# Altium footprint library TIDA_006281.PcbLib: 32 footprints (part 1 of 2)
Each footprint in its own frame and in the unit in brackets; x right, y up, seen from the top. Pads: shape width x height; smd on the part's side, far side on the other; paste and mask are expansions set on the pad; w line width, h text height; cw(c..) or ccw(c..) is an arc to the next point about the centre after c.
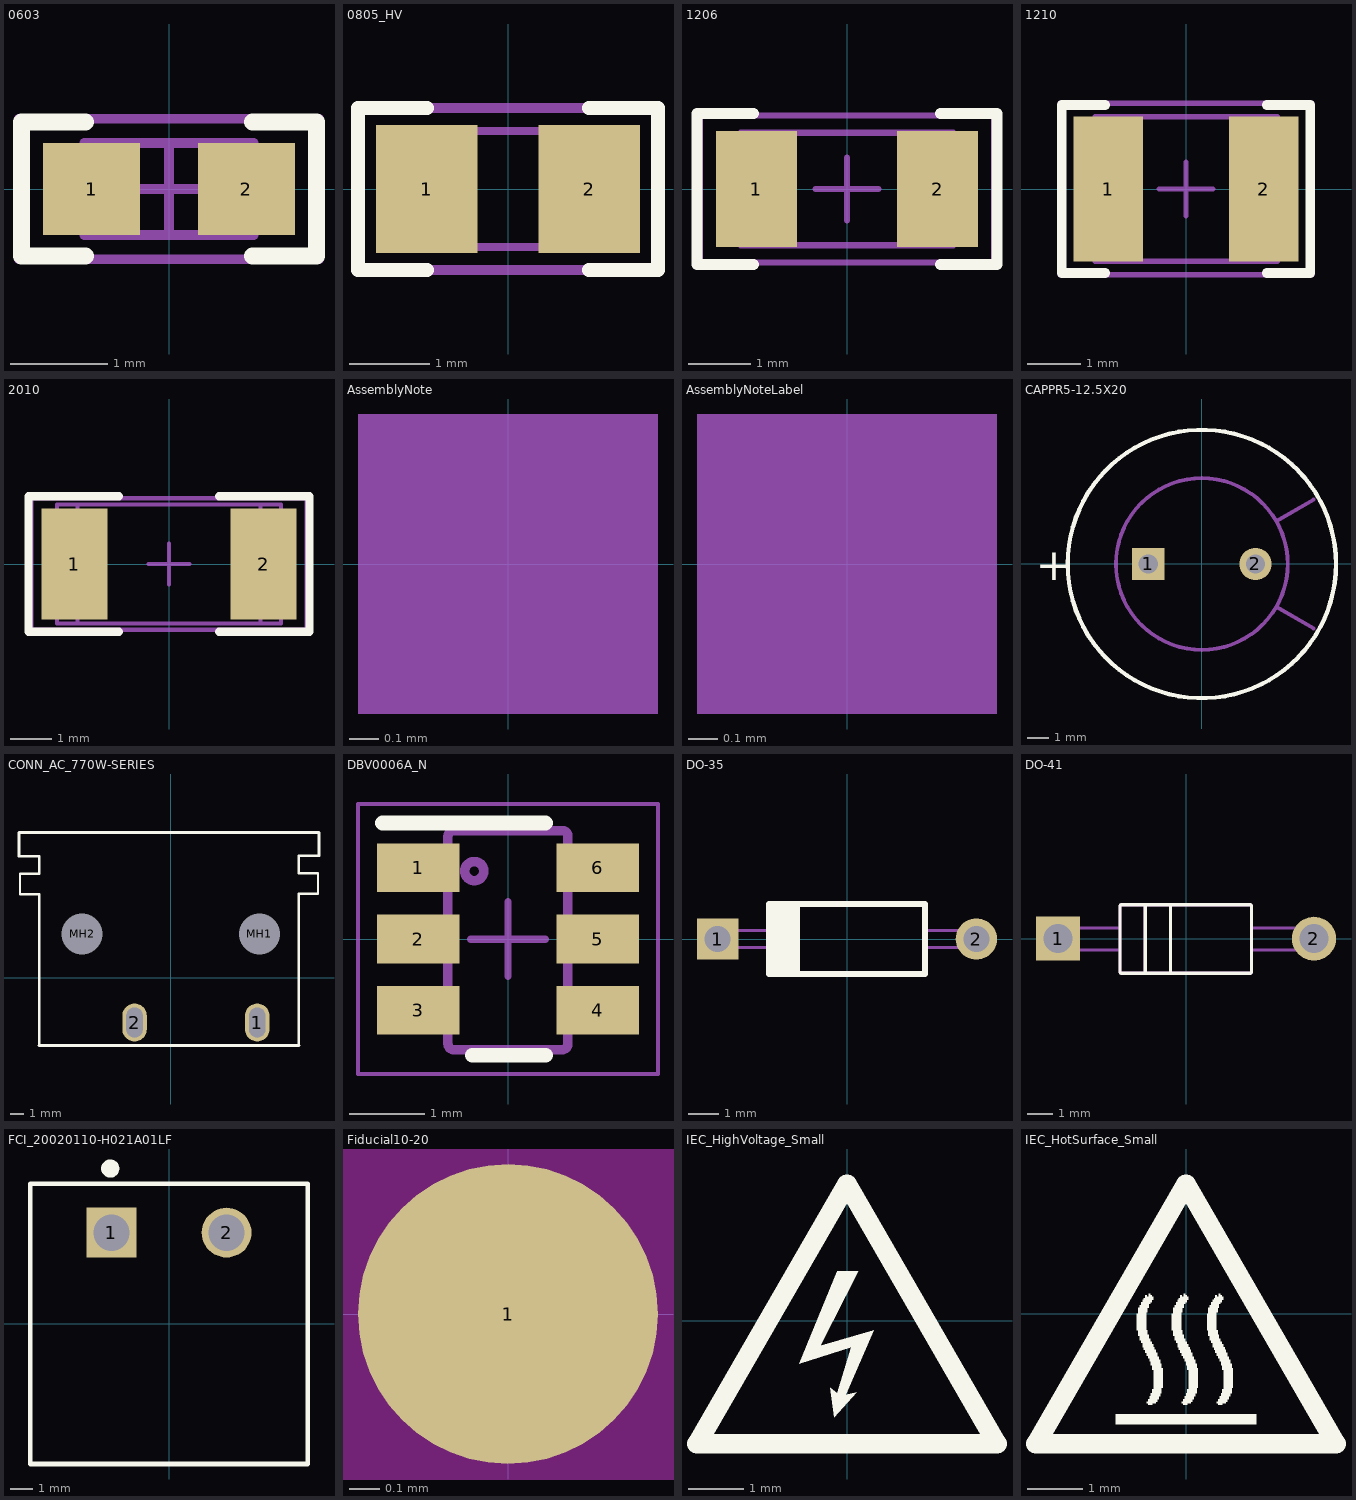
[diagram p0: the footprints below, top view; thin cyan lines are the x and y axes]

## 0603 [mm] "0603 from SM-752 data"
height 0.85
pads (2):
  rect 1x0.95 smd: 1(-0.8,0) 2(0.8,0)
Top Overlay:
  lines w0.178: -0.864,-0.691 -1.524,-0.691 -1.524,0.693 -0.864,0.693 ; 0.864,-0.691 1.524,-0.691 1.524,0.693 0.864,0.693
Mechanical 5:
  lines w0.1: -1.55,-0.725 -1.55,0.725 1.55,0.725 1.55,-0.725 -1.55,-0.725
  text ".Designator" at -1.397,-0.381 h0.76
Mechanical 13:
  lines w0.1: -0.55,-0.475 -0.55,0.475 ; 0.55,-0.475 0.55,0.475 ; -0.875,-0.475 0.875,-0.475 0.875,0.475 -0.875,0.475 -0.875,-0.475
Mechanical 15:
  lines w0.1: -0.475,0 0.475,0 ; 0,-0.475 0,0.475 ; -1.55,-0.725 1.55,-0.725 1.55,0.725 -1.55,0.725 -1.55,-0.725
3D body: height 0.85, standoff 0, extent -0.874,-0.474 -0.551,0.474
3D body: height 0.85, standoff 0, extent -0.549,-0.474 0.549,0.474
3D body: height 0.85, standoff 0, extent 0.551,-0.474 0.874,0.474

## 0805_HV [mil] "0805 with 30mil clearance between pads"
height 57.09
pads (2):
  rect 50x63 smd: 1(-40,0) 2(40,0)
Top Overlay:
  lines w7: -40,-40 -74,-40 -74,0 -74,40 -40,40 ; 40,-40 74,-40 74,0 74,40 40,40
Mechanical 5:
  lines w5: -74,-40 -74,40 74,40 74,-40 -74,-40
  text ".Designator" at -64,-17 h35
Mechanical 13:
  lines w3.94: -25.59,-28.54 -25.59,28.54 ; 25.59,-28.54 25.59,28.54 ; -43.31,-28.54 -43.31,28.54 43.31,28.54 43.31,-28.54 -43.31,-28.54
3D body: height 57.09, standoff 0, extent 25.61,-28.52 43.29,28.52
3D body: height 57.09, standoff 0, extent -25.57,-28.52 25.57,28.52
3D body: height 57.09, standoff 0, extent -43.29,-28.52 -25.61,28.52

## 1206 [mm] "1206 from SM-752 data"
height 1.35
pads (2):
  rect 1.3x1.85 smd: 1(-1.45,0) 2(1.45,0)
Top Overlay:
  lines w0.178: -1.5,-1.21 -2.4,-1.21 -2.4,1.21 -1.5,1.21 ; 1.5,-1.21 2.4,-1.21 2.4,1.21 1.5,1.21
Mechanical 5:
  lines w0.1: -1.7,-0.9 1.7,-0.9 1.7,0.9 -1.7,0.9 -1.7,-0.9
  text ".Designator" at -1.475,-0.4 h0.81
Mechanical 13:
  lines w0.1: -1.2,-0.9 -1.2,0.9 ; 1.2,-0.9 1.2,0.9 ; -1.7,-0.9 1.7,-0.9 1.7,0.9 -1.7,0.9 -1.7,-0.9
Mechanical 15:
  lines w0.1: -0.5,0 0.5,0 ; 0,-0.5 0,0.5 ; -2.35,-1.175 2.35,-1.175 2.35,1.175 -2.35,1.175 -2.35,-1.175
3D body: height 1.35, standoff 0, extent -1.699,-0.899 -1.201,0.899
3D body: height 1.35, standoff 0, extent -1.199,-0.899 1.199,0.899
3D body: height 1.35, standoff 0, extent 1.201,-0.899 1.699,0.899

## 1210 [mm] "1210 from SM-752 data"
height 1.35
pads (2):
  rect 1.3x2.7 smd: 1(-1.45,0) 2(1.45,0)
Top Overlay:
  lines w0.178: -1.511,-1.568 -2.316,-1.568 -2.316,1.568 -1.511,1.568 ; 1.511,-1.568 2.316,-1.568 2.316,1.568 1.511,1.568
Mechanical 5:
  lines w0.1: -1.7,-1.35 -1.7,1.35 1.7,1.35 1.7,-1.35 -1.7,-1.35
  text ".Designator" at -1.4,-0.375 h0.76
Mechanical 13:
  lines w0.1: -1.2,-1.35 -1.2,1.35 ; 1.2,-1.35 1.2,1.35 ; -1.7,-1.35 1.7,-1.35 1.7,1.35 -1.7,1.35 -1.7,-1.35
Mechanical 15:
  lines w0.1: -0.5,0 0.5,0 ; 0,-0.5 0,0.5 ; -2.35,-1.6 2.35,-1.6 2.35,1.6 -2.35,1.6 -2.35,-1.6
3D body: height 1.35, standoff 0, extent 1.201,-1.349 1.699,1.349
3D body: height 1.35, standoff 0, extent -1.199,-1.349 1.199,1.349
3D body: height 1.35, standoff 0, extent -1.699,-1.349 -1.201,1.349

## 2010 [mm] "Chip Capacitor, Body 5.08x2.54mm, IPC Medium Density"
height 1.66
pads (2):
  rect 1.6x2.7 smd: 1(-2.3,0) 2(2.3,0)
Top Overlay:
  lines w0.2: -1.219,-1.65 -3.419,-1.65 -3.419,1.65 -1.219,1.65 ; 1.219,-1.65 3.419,-1.65 3.419,1.65 1.219,1.65
Mechanical 5:
  lines w0.1: -2.73,-1.45 -2.73,1.45 2.73,1.45 2.73,-1.45 -2.73,-1.45
  text ".Designator" at -1.875,-0.5 h1.02
Mechanical 13:
  lines w0.1: -2.23,-1.45 -2.23,1.45 ; 2.23,-1.45 2.23,1.45 ; -2.73,-1.45 2.73,-1.45 2.73,1.45 -2.73,1.45 -2.73,-1.45
Mechanical 15:
  lines w0.1: -0.5,0 0.5,0 ; 0,-0.5 0,0.5 ; -3.35,-1.6 3.35,-1.6 3.35,1.6 -3.35,1.6 -3.35,-1.6
3D body: height 1.66, standoff 0, extent -2.729,-1.449 -2.231,1.449
3D body: height 1.66, standoff 0, extent -2.229,-1.449 2.229,1.449
3D body: height 1.66, standoff 0, extent 2.231,-1.449 2.729,1.449

## AssemblyNote [mm] "Assembly Note"
Mechanical 5:
  rectangle: -0.508,-0.508 0.508,0.508
  text ".Comment" at 1.143,-0.508 h1.02
  text ".Designator" at -4.191,-0.508 h1.02

## AssemblyNoteLabel [mm] "Assembly Note for PCB Labels"
Mechanical 5:
  rectangle: -0.508,-0.508 0.508,0.508
  text ".Designator" at -4.191,-0.508 h1.02
  text "Install label in silkscreened box after final wash.  Text shall be 8 pt font.  Text shall be per the Label Table in the PDF schematic." at 1.143,-0.508 h1.02

## CAPPR5-12.5X20 [mm] "Capacitor, Electrolytic, Radial; Body 12.5 x 20 mm (Dia.xH typ); Pin Spacing 5 mm (typ)"
height 22
pads (2):
  rect 1.5x1.5 hole 0.9: 1(-2.5,0)
  round 1.5 hole 0.9: 2(2.5,0)
Top Overlay:
  circle w0.2: c0,0 r6.25
  text "+" at -7.725,-0.75 h1.5
Mechanical 5:
  circle w0.127: c0,0 r6.25
  text ".Designator" at -1.524,-0.508 h1.02
  text "+" at -7.725,-0.75 h1.5
Mechanical 13:
  circle w0.178: c2.5,0 r0.3
  circle w0.178: c-2.5,0 r0.3
  circle w0.178: c0,0 r4
  lines w0.178: 3.464,-2 5.196,-3 ; 3.464,2 5.196,3
3D body: height 1, standoff -2.54, extent 2.195,-0.305 2.805,0.305
3D body: height 1, standoff -2.54, extent -2.805,-0.305 -2.195,0.305
3D body: height 22, standoff 0, extent 3.463,-3.001 6.01,3.001
3D body: height 22, standoff 0, extent -6.01,-6.01 5.197,6.01
3D body: height 22, standoff 0, extent -4.013,-4.013 5.197,4.013

## CONN_AC_770W-SERIES [mm] "Qualtek Electronics"
height 15
pads (4):
  oval 1.8x2.8 hole 1.2 slot 2.2 at 90 deg: 1(6.35,-3.3) 2(-2.65,-3.3)
  round 2 hole 3 unplated: MH1(6.5,3.2) MH2(-6.5,3.2)
Top Overlay:
  lines w0.178: -11.125,8.9 -9.65,8.9 -9.65,7.625 -11.05,7.625 -11.05,6.125 -9.65,6.125 -9.65,-4.975 ; 9.4,-4.944 9.4,6.156 10.8,6.156 10.8,7.656 9.4,7.656 9.4,8.931 10.875,8.931
  lines w0.2: -11.125,8.9 -11.125,10.6 ; -11.125,10.631 10.875,10.631 10.875,8.931 ; -9.65,-4.975 9.4,-4.975
Mechanical 5:
  lines w0.1: -11.125,10.6 -11.125,8.9 -9.65,8.9 -9.65,7.625 -11.05,7.625 -11.05,6.125 -9.65,6.125 -9.65,-4.975 9.4,-4.975 ; -11.125,10.631 10.875,10.631 10.875,8.931 9.4,8.931 9.4,7.656 10.8,7.656 10.8,6.156 9.4,6.156 9.4,-4.944
  text ".Designator" at -2.032,-0.508 h1.02
3D body: height 22, standoff 0, extent -11,8.9 10.8,10.6
3D body: height 18, standoff 0, extent -11.05,-4.8 10.75,8.925
3D body: height 18, standoff -3.2, extent 5.95,-4.35 6.75,-2.275
3D body: height 18, standoff -3.2, extent -3.05,-4.35 -2.25,-2.275
3D body: height 20.4, standoff 18, extent -11.05,-4.8 10.75,8.925

## DBV0006A_N [mm] "SOT23, 6-Leads, Body 2.9x1.6mm, Pitch 0.95mm, Lead Span 2.8mm, IPC Medium Density"
height 1.45
pads (6):
  rect 1.1x0.65 smd: 1(-1.2,0.95) 2(-1.2,0) 3(-1.2,-0.95) 4(1.2,-0.95) 5(1.2,0) 6(1.2,0.95)
Top Overlay:
  lines w0.2: -1.675,1.55 0.5,1.55 ; -0.475,-1.55 0.5,-1.55
Mechanical 5:
  lines w0.127: 0.724,-1.475 ccw(c0.723,-1.399) 0.8,-1.399 0.8,1.37 ccw(c0.723,1.37) 0.724,1.446 ; 0.723,-1.475 -0.724,-1.475 -0.725,-1.475 cw(c-0.724,-1.399) -0.801,-1.399 -0.801,1.37 cw(c-0.724,1.37) -0.725,1.446 -0.724,1.446 0.723,1.446 ; 0.723,-1.475 0.724,-1.475 ; 0.723,1.446 0.724,1.446 ; -1.423,-1.154 -1.423,-0.78 -1.206,-0.78 -1.113,-0.78 -1.081,-0.78 -0.828,-0.78 -0.801,-0.78 -0.801,-1.154 -0.828,-1.154 -1.081,-1.154 -1.113,-1.154 -1.206,-1.154 -1.423,-1.154 ; -1.423,-0.202 -1.423,0.173 -1.206,0.173 -1.113,0.173 -1.081,0.173 -0.828,0.173 -0.801,0.173 -0.801,-0.202 -0.828,-0.202 -1.081,-0.202 -1.113,-0.202 -1.206,-0.202 -1.423,-0.202 ; -1.423,0.751 -1.423,1.125 -1.206,1.125 -1.113,1.125 -1.081,1.125 -0.828,1.125 -0.801,1.125 -0.801,0.751 -0.828,0.751 -1.081,0.751 -1.113,0.751 -1.206,0.751 -1.423,0.751 ; -0.577,0.906 ccw(c-0.45,0.906) -0.323,0.906 ccw(c-0.45,0.906) -0.577,0.906 ; 0.8,-1.154 0.8,-0.78 0.827,-0.78 1.08,-0.78 1.112,-0.78 1.205,-0.78 1.422,-0.78 1.422,-1.154 1.205,-1.154 1.112,-1.154 1.08,-1.154 0.827,-1.154 0.8,-1.154 ; 0.8,-0.202 0.8,0.173 0.827,0.173 1.08,0.173 1.112,0.173 1.205,0.173 1.422,0.173 1.422,-0.202 1.205,-0.202 1.112,-0.202 1.08,-0.202 0.827,-0.202 0.8,-0.202 ; 0.8,0.751 0.8,1.125 0.827,1.125 1.08,1.125 1.112,1.125 1.205,1.125 1.422,1.125 1.422,0.751 1.205,0.751 1.112,0.751 1.08,0.751 0.827,0.751 0.8,0.751
  text ".Designator" at -0.075,0.925 h0.51
Mechanical 15:
  lines w0.05: -2,-1.8 2,-1.8 2,1.8 -2,1.8 -2,-1.8
  lines w0.1: -0.5,0 0.5,0 ; 0,-0.5 0,0.5
3D body: height 1.11, standoff -0.01, extent -1.422,-1.461 1.422,1.46

## DO-35 [mm] "TH, 2-Leads, Axial, Pin spacing 8.44mm"
height 2.29
pads (2):
  rect 1.35x1.35 hole 0.85: 1(-4.22,0)
  round 1.35 hole 0.85: 2(4.22,0)
Top Overlay:
  rectangle: -2.54,-1.145 -1.541,1.146
  lines w0.2: -2.54,-1.145 2.54,-1.145 2.54,1.145 -2.54,1.145 -2.54,-1.145
Mechanical 5:
  rectangle: -2.54,-1.145 -1.541,1.146
  lines w0.1: -4.223,-0.279 -2.54,-0.279 ; -4.223,-0.279 cw(c-4.221,0.001) -4.222,0.28 -2.539,0.28 ; 2.539,0.28 4.222,0.28 cw(c4.221,0.001) 4.223,-0.279 ; 2.54,-0.279 4.223,-0.279 ; -2.54,-1.145 -2.54,1.145 2.54,1.145 2.54,-1.145 -2.54,-1.145
  text ".Designator" at -2.2,-0.3 h0.7
3D body: height 2.28, standoff 0, extent -2.54,-1.143 2.54,1.143
3D body: height 1.42, standoff 0.86, extent 2.54,-0.279 4.22,0.28
3D body: height 1.42, standoff 0.86, extent -4.22,-0.28 -2.54,0.279
3D body: height 1.42, standoff 0.86, extent -4.497,-0.279 -3.94,0.279
3D body: height 1.14, standoff -2.5, extent -4.498,-0.28 -3.94,0.279
3D body: height 2.29, standoff 0, extent -2.55,-1.148 -1.55,1.148
3D body: height 1.14, standoff -2.5, extent 3.942,-0.279 4.5,0.28
3D body: height 1.42, standoff 0.86, extent 3.943,-0.279 4.5,0.279

## DO-41 [mm] "diode"
height 3
pads (2):
  rect 1.75x1.75 hole 1.15: 1(-5.08,0)
  round 1.75 hole 1.15: 2(5.08,0)
Top Overlay:
  lines w0.127: -1.615,-1.371 -0.615,-1.371 ; -1.615,1.347 -0.615,1.347 ; -2.615,-1.322 ccw(c-2.565,-1.322) -2.565,-1.372 -1.615,-1.372 -1.615,-0.012 -1.615,1.348 -2.565,1.348 ccw(c-2.565,1.298) -2.615,1.298 -2.615,-0.012 -2.615,-1.322 ; -0.615,-1.372 -0.615,1.348 2.545,1.348 cw(c2.545,1.298) 2.595,1.298 2.595,-1.322 cw(c2.545,-1.322) 2.545,-1.372 -0.615,-1.372
Mechanical 5:
  lines w0.127: -2.615,-0.444 -4.09,-0.444 -5.09,-0.444 cw(c-5.09,-0.012) -5.522,-0.012 cw(c-5.09,-0.012) -5.09,0.42 -4.09,0.42 -2.615,0.42 ; -1.615,-1.371 -0.615,-1.371 ; -1.615,1.347 -0.615,1.347 ; 2.595,-0.444 4.07,-0.444 5.07,-0.444 ccw(c5.07,-0.012) 5.502,-0.012 ccw(c5.07,-0.012) 5.07,0.42 4.07,0.42 2.595,0.42 ; -2.615,-1.322 ccw(c-2.565,-1.322) -2.565,-1.372 -1.615,-1.372 -1.615,-0.012 -1.615,1.348 -2.565,1.348 ccw(c-2.565,1.298) -2.615,1.298 -2.615,-0.012 -2.615,-1.322 ; -0.615,-1.372 2.545,-1.372 ccw(c2.545,-1.322) 2.595,-1.322 2.595,1.298 ccw(c2.545,1.298) 2.545,1.348 -0.615,1.348 -0.615,-1.372
  text ".Designator" at -0.178,-0.254 h0.51
3D body: height 2.72, standoff -2.6, extent -5.512,-1.36 5.512,1.36

## FCI_20020110-H021A01LF [mm] "FCI"
height 8.8
pads (2):
  rect 2.2x2.2 hole 1.6 paste+0 mask+0.05: 1(-2.54,4.03)
  round 2.2 hole 1.6 paste+0 mask+0.05: 2(2.54,4.03)
Top Overlay:
  circle w0.4: c-2.594,6.86 r0.2
  lines w0.2: -6.13,-6.18 -6.13,6.18 6.13,6.18 6.13,-6.18 -6.13,-6.18
Mechanical 5:
  region: -1.555,3.05 -3.53,3.05 -3.53,5.025 -1.555,5.025
  lines w0.1: -6.13,-6.18 -6.13,6.18 6.13,6.18 6.13,-6.18 -6.13,-6.18
  text ".Designator" at -1.9,-0.475 h1.02
3D body: height 8.67, standoff -3.32, extent -6.08,-6 6.08,6

## Fiducial10-20 [mm]
pads (1):
  round 1 smd mask+0.5: 1(0,0)
Top Layer keep-out:
  circle w1.178: c0,0 r0.5

## IEC_HighVoltage_Small [mm]
Top Overlay:
  region: -0.178,0.889 0.203,0.889 -0.483,-0.457 0.483,-0.178 -0.025,-1.346 0.178,-1.295 -0.229,-1.753 -0.305,-1.219 -0.178,-1.321 0.076,-0.483 -0.864,-0.787
  lines w0.356: -2.718,-2.235 2.718,-2.235 0,2.472 -2.718,-2.235

## IEC_HotSurface_Small [mm]
Top Overlay:
  drawing of 10 lines, arcs and shapes, not listed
